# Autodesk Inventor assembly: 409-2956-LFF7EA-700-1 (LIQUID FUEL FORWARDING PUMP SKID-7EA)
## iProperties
Created: 2010-06
Part Number: 409-2956-LFF7EA-700-1 (LIQUID FUEL FORWARDING PUMP SKID-7EA)
Document SubType Name: Assembly
Designer: S. Boerckel
Mass: 3.2744e+06 g
Surface Area: 831107 cm^2
Volume: 431877 cm^3
Density: 7.58178 g/cm^3
Description: MECHANICAL
Material: ASSEMBLY
Author: S. Boerckel
Revision Number: B
Title: MECHANICAL
Subject: LIQUID FUEL FORWARDING PUMP SKID-7EA
